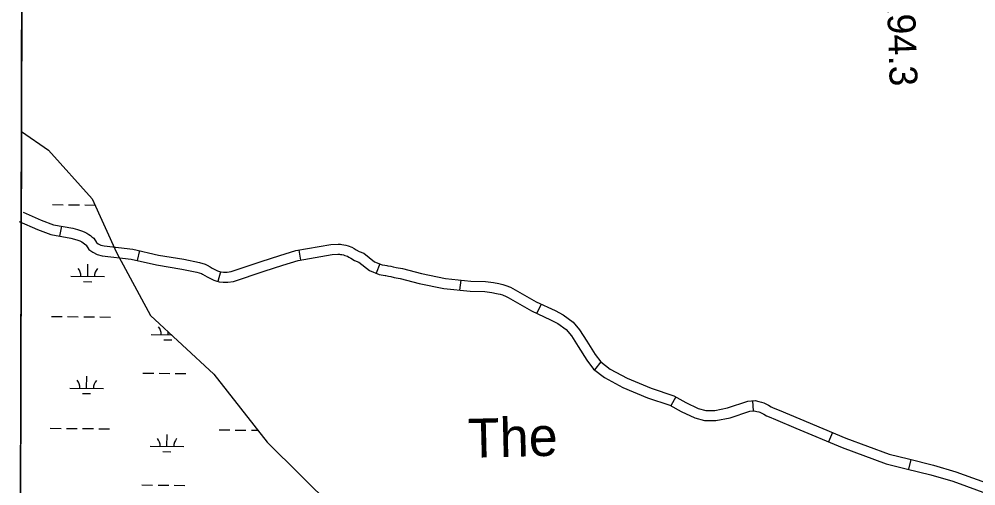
# Model space of a CAD drawing. Extents: x 3192986 to 3230865, y 867483 to 892886.
# Drawn here: x 3197187 to 3200032, y 874735 to 876124 of the extents above; entities that cross this region are included whole.
import ezdxf

# ---------------------------------------------------------------- set-up
doc = ezdxf.new("R2010")
doc.units = 0
for name, color, linetype in [('V-GRID-FRAM', 7, 'Continuous'), ('V-RIVR-IDEN', 7, 'Continuous'), ('V-RIVR-RANG-IDEN', 7, 'Continuous'), ('V-ROAD-CNTR', 7, 'Continuous'), ('V-SITE-VEGE', 7, 'Continuous'), ('V-WETL-SWMP', 7, 'Continuous')]:
    doc.layers.add(name, color=color, linetype=linetype)

msp = doc.modelspace()

# ---------------------------------------------------------------- linework, layer by layer
at = {"layer": 'V-GRID-FRAM'}
msp.add_lwpolyline([(3197186.7, 872920.9), (3197229, 891108.8)], dxfattribs=at)
at = {"layer": 'V-ROAD-CNTR'}
for p, q in [((3197312.3, 875508.2), (3197307, 875478.6)), ((3197544.2, 875435.3), (3197537.5, 875406.1)), ((3198018.2, 875437), (3198023.5, 875407.4)), ((3198259.4, 875396.3), (3198248.2, 875368.4)), ((3197785.2, 875372.7), (3197777.2, 875343.8)), ((3198499.9, 875347.6), (3198496.7, 875317.8)), ((3198739.5, 875276.1), (3198726.8, 875249)), ((3198916.3, 875104.4), (3198898.1, 875080.5)), ((3199139.6, 875000.2), (3199124.9, 874974)), ((3199367.6, 874988.7), (3199369.9, 874958.8)), ((3199605.4, 874894.1), (3199593.7, 874866.5)), ((3199839.2, 874813.9), (3199832.1, 874784.7))]:
    msp.add_line(p, q, dxfattribs=at)
for points in [[(3197198.8, 875549.9), (3197252.6, 875526.1), (3197289.2, 875512.3), (3197346.4, 875502.1), (3197360.2, 875498.7), (3197372.3, 875494.5), (3197380.2, 875491), (3197388, 875487), (3197393.5, 875483.3), (3197398.5, 875480), (3197402.9, 875476.5), (3197408.5, 875472.7), (3197416.5, 875459.6), (3197421.9, 875455.9), (3197429.7, 875451.6), (3197439.1, 875449.3), (3197525.2, 875439.7), (3197601.2, 875422.3), (3197676.2, 875410.1), (3197723.1, 875400.5), (3197739.6, 875395.2), (3197746.2, 875392.2), (3197754.6, 875387), (3197760.9, 875383), (3197768.7, 875378.9), (3197776.7, 875375.2), (3197780, 875374.1), (3197787.1, 875372.2), (3197794.7, 875371.2), (3197805, 875371.5), (3197817.5, 875373.1), (3197906.3, 875402.8), (3197961.8, 875420.9), (3198010, 875435.5), (3198113.8, 875453.8), (3198135.3, 875455), (3198142.2, 875454.4), (3198146.7, 875453.8), (3198152, 875453), (3198158.5, 875451.6), (3198164.8, 875449.9), (3198176, 875445.9), (3198182.9, 875442), (3198189.2, 875438), (3198197.5, 875432.9), (3198212.1, 875427.7), (3198243.9, 875402.5), (3198266.3, 875393.5), (3198273.9, 875392.1), (3198280, 875391.2), (3198283.3, 875390.6), (3198291.7, 875388.7), (3198298.8, 875387.2), (3198307.6, 875385), (3198326.5, 875382), (3198383.5, 875366.9), (3198454.6, 875352.4), (3198530.1, 875344.4), (3198573.8, 875343.6), (3198597.5, 875340.6), (3198613, 875337.2), (3198617.6, 875336.3), (3198625.1, 875334.5), (3198633.8, 875332), (3198647.7, 875326.3), (3198655.4, 875322.2), (3198724.6, 875283.1), (3198781, 875256.8), (3198804.8, 875244), (3198834.1, 875222.6), (3198853.2, 875199.4), (3198875, 875166.2), (3198899.5, 875126.8), (3198916.6, 875104.1), (3198944.2, 875083.1), (3198995.4, 875055.6), (3199066.6, 875025.9), (3199133.7, 875003.4), (3199169.3, 874983.5), (3199206.6, 874966.1), (3199228.7, 874960.1), (3199256.2, 874960.2), (3199293.2, 874967.4), (3199353.7, 874987.6), (3199375.7, 874989.3), (3199387.1, 874986.2), (3199394.8, 874984.9), (3199401.8, 874982.3), (3199415.5, 874975.2), (3199423.3, 874970.9), (3199429.3, 874968), (3199447.2, 874961.1), (3199508.8, 874934.8), (3199645.4, 874877.3), (3199774.5, 874830), (3199831.8, 874815.7), (3199906.1, 874797.5), (3199972.9, 874777.7), (3200085.7, 874736.9)], [(3197186.7, 875522.4), (3197241.2, 875498.4), (3197281.2, 875483.3), (3197340.2, 875472.7), (3197351.7, 875469.9), (3197361.4, 875466.6), (3197367.2, 875464), (3197372.7, 875461.1), (3197377, 875458.3), (3197380.8, 875455.8), (3197385, 875452.3), (3197386.3, 875451.5), (3197394.2, 875438.6), (3197406.2, 875430.3), (3197418.6, 875423.5), (3197433.7, 875419.7), (3197520.2, 875410.1), (3197595.5, 875392.8), (3197670.8, 875380.6), (3197715.4, 875371.5), (3197728.7, 875367.2), (3197732.1, 875365.6), (3197738.7, 875361.6), (3197745.8, 875357.1), (3197755.4, 875352), (3197765.6, 875347.3), (3197771.2, 875345.4), (3197781.3, 875342.6), (3197793.3, 875341.2), (3197807.4, 875341.5), (3197824.3, 875343.8), (3197915.8, 875374.3), (3197970.8, 875392.3), (3198017, 875406.3), (3198117.2, 875423.9), (3198134.8, 875424.9), (3198139.1, 875424.5), (3198142.6, 875424.1), (3198146.5, 875423.5), (3198151.3, 875422.4), (3198155.8, 875421.2), (3198163.5, 875418.5), (3198167.5, 875416.2), (3198173.4, 875412.5), (3198184.5, 875405.7), (3198197.4, 875401.1), (3198228.6, 875376.3), (3198257.8, 875364.6), (3198269, 875362.4), (3198275, 875361.6), (3198277.3, 875361.2), (3198285.4, 875359.4), (3198291.9, 875358), (3198301.6, 875355.5), (3198320.3, 875352.6), (3198376.7, 875337.6), (3198450, 875322.7), (3198528.2, 875314.4), (3198571.6, 875313.7), (3198592.4, 875311), (3198606.9, 875307.8), (3198611.2, 875307), (3198617.4, 875305.5), (3198623.9, 875303.6), (3198635, 875299.1), (3198641, 875295.9), (3198710.8, 875256.4), (3198767.5, 875229.9), (3198788.8, 875218.5), (3198813.3, 875200.7), (3198829, 875181.6), (3198849.7, 875150), (3198874.8, 875109.9), (3198895.1, 875082.8), (3198927.9, 875057.8), (3198982.5, 875028.5), (3199056, 874997.8), (3199121.5, 874975.9), (3199155.6, 874956.7), (3199196.3, 874937.8), (3199224.7, 874930), (3199259.2, 874930.3), (3199300.9, 874938.3), (3199359.6, 874958), (3199372.9, 874959), (3199380.7, 874956.9), (3199387, 874955.8), (3199389.5, 874954.9), (3199401.3, 874948.7), (3199409.6, 874944.2), (3199417.4, 874940.5), (3199435.9, 874933.3), (3199497.1, 874907.2), (3199634.4, 874849.4), (3199765.7, 874801.2), (3199824.7, 874786.6), (3199898.2, 874768.6), (3199963.5, 874749.1), (3200074.9, 874708.9)]]:
    msp.add_lwpolyline(points, dxfattribs=at)
at = {"layer": 'V-SITE-VEGE'}
msp.add_line((3197196.8, 877299), (3197190.2, 874440.2), dxfattribs=at)
at = {"layer": 'V-WETL-SWMP'}
for p, q in [((3197190.2, 874440.3), (3197193.3, 875790)), ((3197193.3, 875790), (3197273.6, 875734.3)), ((3197273.6, 875734.3), (3197403.9, 875589.5)), ((3197403.9, 875589.5), (3197476.2, 875430.2)), ((3197285.9, 875572.2), (3197317.9, 875571.9)), ((3197333.9, 875571.8), (3197365.9, 875571.4)), ((3197381.9, 875571.3), (3197412.3, 875571)), ((3197476.2, 875430.2), (3197577.5, 875241.9)), ((3197390.7, 875358.6), (3197391, 875394.6)), ((3197340.7, 875359.1), (3197440.7, 875358.1)), ((3197378.5, 875343.3), (3197402.5, 875343)), ((3197577.5, 875241.9), (3197765.6, 875068.2)), ((3197282.7, 875239.6), (3197314.7, 875239.3)), ((3197330.7, 875239.1), (3197362.7, 875238.8)), ((3197378.7, 875238.6), (3197410.7, 875238.3)), ((3197426.7, 875238.2), (3197458.7, 875237.8)), ((3197579.5, 875185.9), (3197638.8, 875185.3)), ((3197629.5, 875185.4), (3197629.6, 875193.9)), ((3197617.3, 875170.1), (3197641.3, 875169.9)), ((3197554.9, 875070.7), (3197586.9, 875070.4)), ((3197602.9, 875070.3), (3197634.9, 875069.9)), ((3197387.4, 875025.9), (3197387.8, 875061.9)), ((3197650.9, 875069.8), (3197682.9, 875069.5)), ((3197765.6, 875068.2), (3197924.8, 874865.4)), ((3197337.4, 875026.4), (3197437.4, 875025.4)), ((3197375.3, 875010.6), (3197399.3, 875010.4)), ((3197279.4, 874906.9), (3197311.4, 874906.6)), ((3197327.4, 874906.4), (3197359.4, 874906.1)), ((3197375.4, 874906), (3197407.4, 874905.7)), ((3197423.4, 874905.5), (3197455.4, 874905.2)), ((3197781.3, 874902), (3197813.3, 874901.7)), ((3197829.3, 874901.5), (3197861.3, 874901.2)), ((3197877.3, 874901.1), (3197897, 874900.9)), ((3197626.2, 874852.8), (3197626.6, 874888.8)), ((3197576.2, 874853.3), (3197676.2, 874852.3)), ((3197924.8, 874865.4), (3198126.6, 874665.5)), ((3197614.1, 874837.5), (3197638.1, 874837.2)), ((3197551.7, 874738.1), (3197583.7, 874737.8)), ((3197599.7, 874737.6), (3197631.7, 874737.3)), ((3197647.7, 874737.1), (3197679.7, 874736.8))]:
    msp.add_line(p, q, dxfattribs=at)
for centre, start, end in [((3197335.4, 875359.6), 358.6685, 40.2121), ((3197445.9, 875358.5), 138.6685, 180.2121), ((3197574.2, 875186.4), 358.6685, 40.2121), ((3197332.2, 875026.9), 358.6685, 40.2121), ((3197442.7, 875025.9), 138.6685, 180.2121), ((3197571, 874853.8), 358.6685, 40.2121), ((3197681.5, 874852.7), 138.6685, 180.2121)]:
    msp.add_arc(centre, 35.2, start, end, dxfattribs=at)

# ---------------------------------------------------------------- texts
at = {"layer": 'V-RIVR-IDEN'}
msp.add_text('The', height=116, rotation=1.404, dxfattribs=at).set_placement((3198522.6, 874818.8))
at = {"layer": 'V-RIVR-RANG-IDEN'}
msp.add_text('R-294.3', height=83, rotation=271.9666, dxfattribs=at).set_placement((3199762.8, 876317.8))

doc.saveas('drawing.dxf')
